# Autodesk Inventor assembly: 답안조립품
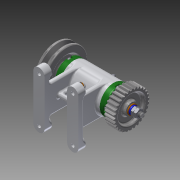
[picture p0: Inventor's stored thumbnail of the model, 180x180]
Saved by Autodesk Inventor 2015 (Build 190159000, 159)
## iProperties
Created: 2015-11
Part Number: 답안조립품
Document SubType Name: Assembly
Designer: Administrator
Author: Administrator
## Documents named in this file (16)
- C:\Users\Administrator\Desktop\451109V1034\답안조립품.iam
- C:\Users\Administrator\Desktop\451109V1034\본체.ipt
- C:\Users\Administrator\Desktop\451109V1034\커버.ipt
- C:\Users\Administrator\Desktop\451109V1034\베어링 15 x 32 x 9.ipt
- C:\Users\Administrator\Desktop\451109V1034\축.ipt
- C:\Users\Administrator\Desktop\451109V1034\오일 실 15 25 7.ipt
- C:\Users\Administrator\Desktop\451109V1034\와셔 6x11.5.ipt
- C:\Users\Administrator\Desktop\451109V1034\볼트 M 6 x 8.ipt
- C:\Users\Administrator\Desktop\451109V1034\볼트 M4 x 12.ipt
- C:\Users\Administrator\Desktop\451109V1034\키 3 x 3 x 12.ipt
- C:\Users\Administrator\Desktop\451109V1034\스퍼기어.ipt
- C:\Users\Administrator\Desktop\451109V1034\V벨트풀리.ipt
- C:\Users\Administrator\Desktop\451109V1034\와셔 8x17.ipt
- C:\Users\Administrator\Desktop\451109V1034\스프링와셔 8.ipt
- C:\Users\Administrator\Desktop\451109V1034\너트 M 8.ipt
- C:\Users\Administrator\Desktop\451109V1034\니플 M 6 x 0.75.ipt
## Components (11 placed, 3 different names)
1. KS B 2023 6002 - 15 x 32 x 9:1
2. KS B 2023 6002 - 15 x 32 x 9:2
3. ISO 4762 M4 x 12:1 — 각도:2
4. ISO 4762 M4 x 12:2 — 각도:3
5. ISO 4762 M4 x 12:3 — 각도:4
6. ISO 4762 M4 x 12:4 — 각도:5
7. ISO 4762 M4 x 12:5 — 각도:8
8. ISO 4762 M4 x 12:6 — 각도:9
9. ISO 4762 M4 x 12:7 — 각도:7
10. ISO 4762 M4 x 12:8 — 각도:6
11. V벨트풀리:1 — 각도:11
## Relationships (9: Angle 9)
- 각도:2 [Angle]: ISO 4762 M4 x 12:1
- 각도:3 [Angle]: ISO 4762 M4 x 12:2
- 각도:4 [Angle]: ISO 4762 M4 x 12:3
- 각도:5 [Angle]: ISO 4762 M4 x 12:4
- 각도:6 [Angle]: ISO 4762 M4 x 12:8
- 각도:7 [Angle]: ISO 4762 M4 x 12:7
- 각도:8 [Angle]: ISO 4762 M4 x 12:5
- 각도:9 [Angle]: ISO 4762 M4 x 12:6
- 각도:11 [Angle]: V벨트풀리:1
